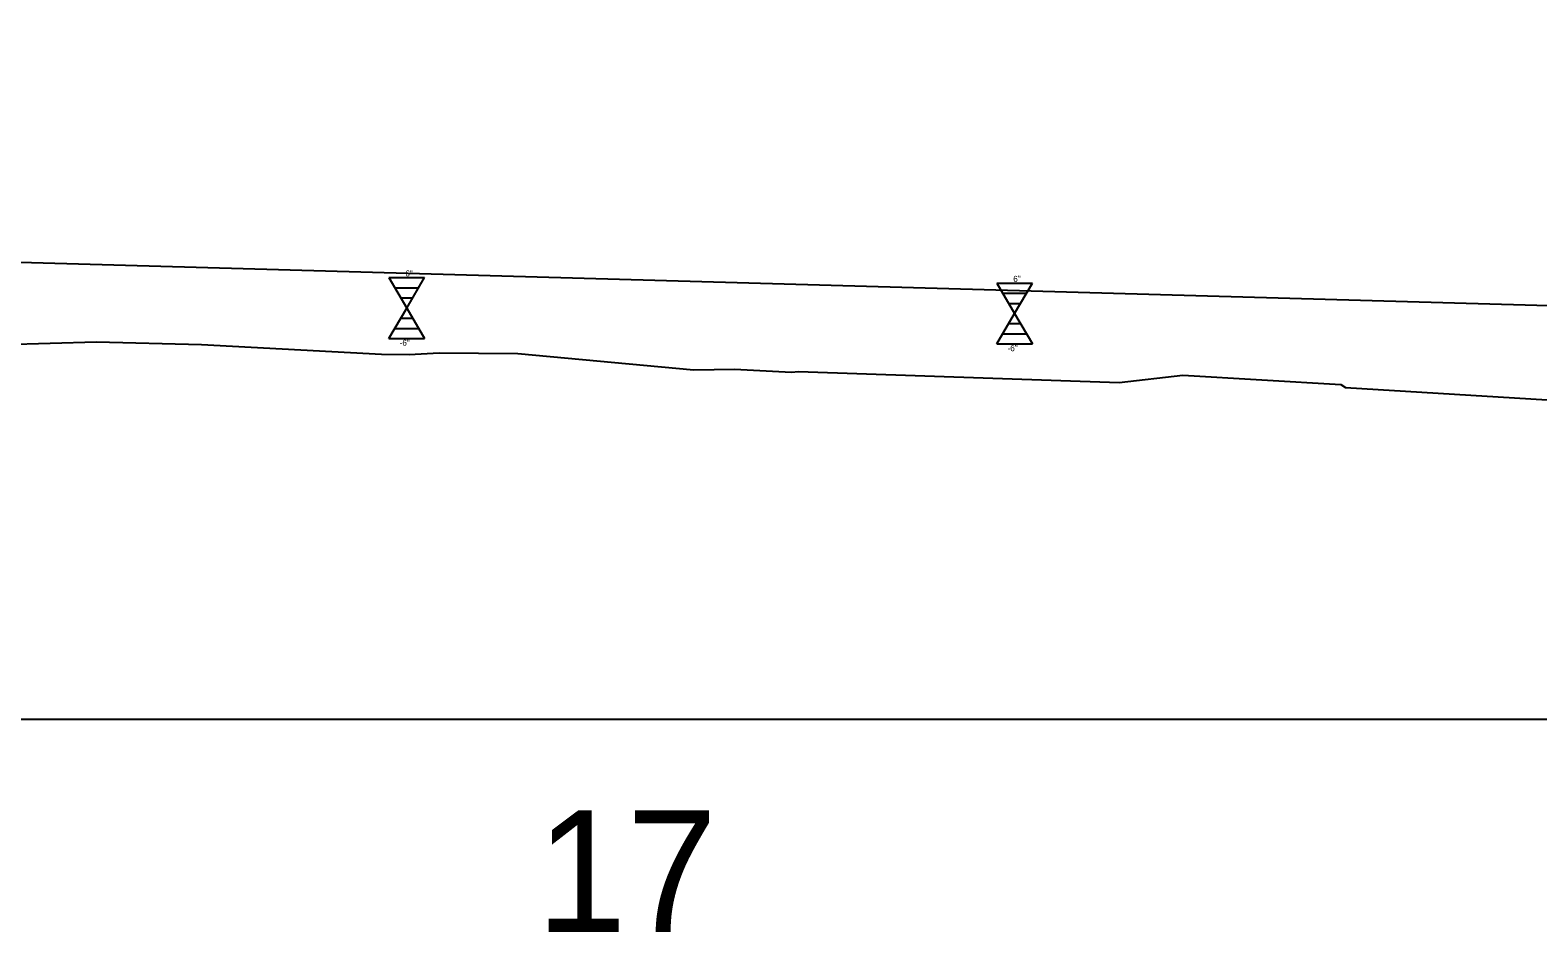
# Model space of a CAD drawing. Extents: x 573468 to 580768, y -57414 to -51768.
# Drawn here: x 574423.3 to 574547.3, y -53422.8 to -53348.7 of the extents above; entities that cross this region are included whole.
import ezdxf

# ---------------------------------------------------------------- set-up
doc = ezdxf.new("R2010")
doc.units = 0
for name, color, linetype in [('Exist Profile Cell', 7, 'Continuous'), ('Exist Vertical Profile Ground Line', 7, 'Continuous'), ('Exist Vertical Profile Horizontal Axis Label Major', 7, 'Continuous'), ('Pattern 2', 7, 'Continuous'), ('Prop Vertical Profile Grade', 7, 'Continuous')]:
    doc.layers.add(name, color=color, linetype=linetype)

msp = doc.modelspace()

# ---------------------------------------------------------------- linework, layer by layer
at = {"layer": 'Exist Profile Cell'}
msp.add_line((573502.62, -53405.32), (576177.52, -53405.32), dxfattribs=at)
at = {"layer": 'Exist Vertical Profile Ground Line'}
msp.add_lwpolyline([(574421.17, -53374.51), (574428.79, -53374.31), (574437.42, -53374.51), (574452.24, -53375.3), (574454.51, -53375.34), (574456.99, -53375.2), (574463.46, -53375.26), (574477.93, -53376.59), (574481.27, -53376.55), (574485.95, -53376.79), (574486.53, -53376.73), (574512.92, -53377.63), (574518.15, -53377.03), (574531.15, -53377.8), (574531.52, -53378.06), (574554.39, -53379.46)], dxfattribs=at)
at = {"layer": 'Pattern 2'}
for p, q in [((574452.84, -53369.02), (574455.77, -53369.02)), ((574452.84, -53369.02), (574454.31, -53371.52)), ((574453.33, -53369.85), (574455.29, -53369.85)), ((574454.31, -53371.52), (574455.77, -53369.02)), ((574502.84, -53369.47), (574505.77, -53369.47)), ((574502.84, -53369.47), (574504.31, -53371.97)), ((574504.31, -53371.97), (574505.77, -53369.47)), ((574453.82, -53370.69), (574454.8, -53370.69)), ((574503.33, -53370.3), (574505.29, -53370.3)), ((574503.82, -53371.14), (574504.8, -53371.14)), ((574452.84, -53374.02), (574454.31, -53371.52)), ((574453.82, -53372.35), (574454.8, -53372.35)), ((574454.31, -53371.52), (574455.77, -53374.02)), ((574502.84, -53374.47), (574504.31, -53371.97)), ((574504.31, -53371.97), (574505.77, -53374.47)), ((574453.33, -53373.19), (574455.29, -53373.19)), ((574503.33, -53373.64), (574505.29, -53373.64)), ((574503.82, -53372.8), (574504.8, -53372.8)), ((574452.84, -53374.02), (574455.77, -53374.02)), ((574502.84, -53374.47), (574505.77, -53374.47))]:
    msp.add_line(p, q, dxfattribs=at)
at = {"layer": 'Prop Vertical Profile Grade'}
msp.add_line((573747.58, -53348.67), (574576.43, -53372.11), dxfattribs=at)

# ---------------------------------------------------------------- texts
at = {"layer": 'Exist Vertical Profile Horizontal Axis Label Major'}
msp.add_text('17', height=10, dxfattribs=at).set_placement((574464.97, -53422.82))
at = {"layer": 'Pattern 2'}
for s, p in [('6"', (574454.2, -53368.92)), ('6"', (574504.2, -53369.37)), ('-6"', (574453.73, -53374.62)), ('-6"', (574503.73, -53375.07))]:
    msp.add_text(s, height=0.5, rotation=360, dxfattribs=at).set_placement(p)

doc.saveas('drawing.dxf')
